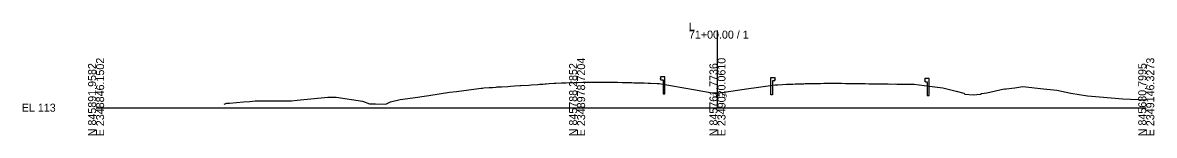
# Model space of a CAD drawing. Extents: x -26 to 2348767, y -10 to 845205.
# Drawn here: x 2164.2 to 2560.2, y 6490.3 to 6529.8 of the extents above; entities that cross this region are included whole.
import ezdxf

# ---------------------------------------------------------------- set-up
doc = ezdxf.new("R2010")
doc.units = 0
for name, color, linetype in [('Exist Cross Section Cell', 7, 'Continuous'), ('Exist XS Center Line Elevation Label', 7, 'Continuous'), ('Exist XS Ground Line', 7, 'Continuous'), ('Prop CMT Guardrail Graphics', 7, 'Continuous')]:
    doc.layers.add(name, color=color, linetype=linetype)

msp = doc.modelspace()

# ---------------------------------------------------------------- linework, layer by layer
at = {"layer": 'Exist Cross Section Cell'}
for p, q in [((2407.33, 6500), (2407.33, 6526.98)), ((2189.93, 6500), (2358.22, 6500)), ((2358.22, 6500), (2407.33, 6500)), ((2407.33, 6500), (2557.33, 6500))]:
    msp.add_line(p, q, dxfattribs=at)
at = {"layer": 'Exist XS Ground Line'}
msp.add_lwpolyline([(2234.77, 6501.29), (2235.73, 6501.56), (2236.65, 6501.57), (2241.48, 6502), (2243.77, 6502.17), (2245.57, 6502.35), (2257.71, 6502.45), (2258.27, 6502.45), (2260.25, 6502.63), (2270.96, 6503.63), (2273.95, 6503.67), (2283.09, 6502.28), (2285.56, 6501.35), (2287.68, 6501.32), (2291.32, 6501.26), (2292.94, 6502.03), (2296.35, 6502.84), (2300.77, 6503.43), (2306.35, 6504.25), (2313.6, 6505.39), (2316.07, 6505.7), (2324.68, 6506.87), (2325.16, 6506.88), (2325.59, 6506.91), (2327.44, 6507.05), (2328.6, 6507.12), (2329.89, 6507.24), (2330.3, 6507.26), (2331.73, 6507.33), (2333.98, 6507.47), (2334.92, 6507.53), (2336.31, 6507.61), (2338.19, 6507.73), (2338.56, 6507.75), (2341.27, 6507.93), (2342.13, 6508), (2344.44, 6508.17), (2345.2, 6508.23), (2346.18, 6508.29), (2347, 6508.35), (2347.44, 6508.38), (2348.45, 6508.45), (2350.21, 6508.53), (2350.81, 6508.57), (2352.75, 6508.68), (2353.3, 6508.71), (2354.3, 6508.74), (2357.18, 6508.81), (2358.41, 6508.84), (2360.21, 6508.89), (2363.2, 6508.96), (2365.26, 6508.99), (2366.17, 6508.99), (2366.71, 6508.99), (2367.67, 6508.97), (2369.11, 6508.95), (2370.33, 6508.93), (2372.29, 6508.9), (2373.98, 6508.86), (2375.06, 6508.84), (2376.17, 6508.82), (2377.4, 6508.79), (2378.04, 6508.76), (2379.41, 6508.73), (2381.26, 6508.68), (2381.63, 6508.67), (2383.04, 6508.62), (2383.94, 6508.6), (2386.2, 6508.49), (2386.93, 6508.43), (2398.92, 6506.39), (2406.76, 6505.02), (2407.33, 6505.1), (2416.65, 6506.47), (2427.45, 6508.04), (2428.08, 6508.02), (2428.39, 6508.05), (2430.07, 6508.14), (2431.43, 6508.2), (2432.48, 6508.24), (2433.71, 6508.28), (2434.46, 6508.31), (2437.48, 6508.41), (2438.01, 6508.43), (2440.39, 6508.47), (2441.8, 6508.5), (2442.75, 6508.51), (2443.37, 6508.52), (2444.55, 6508.53), (2446.39, 6508.54), (2449.46, 6508.54), (2449.82, 6508.53), (2450.7, 6508.53), (2452.12, 6508.52), (2453.48, 6508.51), (2455.65, 6508.49), (2457.18, 6508.46), (2458.22, 6508.44), (2459.03, 6508.43), (2460.25, 6508.41), (2461.21, 6508.39), (2461.52, 6508.38), (2461.82, 6508.37), (2464.12, 6508.35), (2464.85, 6508.34), (2466.23, 6508.33), (2467.09, 6508.31), (2467.79, 6508.29), (2469.62, 6508.3), (2470.04, 6508.29), (2471.02, 6508.28), (2473.05, 6508.26), (2474.09, 6508.24), (2475.51, 6508.19), (2476.18, 6508.19), (2479.63, 6507.78), (2486.2, 6506.93), (2490.81, 6505.82), (2493.5, 6505.04), (2493.86, 6504.75), (2496.76, 6504.48), (2499.37, 6504.77), (2499.7, 6504.91), (2501.57, 6505.24), (2507.66, 6506.65), (2507.98, 6506.47), (2508.34, 6506.63), (2511.4, 6506.9), (2514.16, 6507.41), (2521.4, 6506.64), (2526.04, 6506.11), (2531, 6505.13), (2536.76, 6504.11), (2540.94, 6503.75), (2549.11, 6503.15), (2557.33, 6502.8)], dxfattribs=at)
at = {"layer": 'Prop CMT Guardrail Graphics'}
for p, q in [((2387.6, 6510.86), (2387.33, 6510.57)), ((2387.33, 6510.57), (2387.6, 6510.28)), ((2387.6, 6510.28), (2387.33, 6509.99)), ((2387.33, 6509.99), (2387.6, 6509.7)), ((2388.94, 6510.86), (2387.6, 6510.86)), ((2387.6, 6509.7), (2388.27, 6509.7)), ((2388.27, 6509.7), (2388.27, 6504.86)), ((2388.94, 6504.86), (2388.94, 6510.86)), ((2425.94, 6504.55), (2425.94, 6510.55)), ((2425.94, 6510.55), (2427.27, 6510.55)), ((2427.27, 6509.39), (2426.6, 6509.39)), ((2426.6, 6509.39), (2426.6, 6504.55)), ((2427.27, 6510.55), (2427.54, 6510.26)), ((2427.54, 6510.26), (2427.27, 6509.97)), ((2427.27, 6509.97), (2427.54, 6509.68)), ((2427.54, 6509.68), (2427.27, 6509.39)), ((2480.07, 6510.26), (2479.8, 6509.97)), ((2479.8, 6509.97), (2480.07, 6509.68)), ((2480.07, 6509.68), (2479.8, 6509.39)), ((2479.8, 6509.39), (2480.07, 6509.09)), ((2481.41, 6510.26), (2480.07, 6510.26)), ((2481.41, 6504.26), (2481.41, 6510.26)), ((2480.07, 6509.09), (2480.74, 6509.09)), ((2480.74, 6509.09), (2480.74, 6504.26)), ((2388.27, 6504.86), (2388.94, 6504.86)), ((2426.6, 6504.55), (2425.94, 6504.55)), ((2480.74, 6504.26), (2481.41, 6504.26))]:
    msp.add_line(p, q, dxfattribs=at)

# ---------------------------------------------------------------- texts
at = {"layer": 'Exist Cross Section Cell'}
for s, p in [('L', (2397.33, 6526.98)), ('71+00.00 / 1', (2397.33, 6524.18)), ('EL 113', (2163.93, 6498.6))]:
    msp.add_text(s, height=2.8, dxfattribs=at).set_placement(p)
for s, p in [('E 2348846.1502', (2192.73, 6490)), ('E 2348978.7204', (2361.02, 6490)), ('E 2349020.0610', (2410.13, 6490)), ('E 2349146.3273', (2560.13, 6490)), ('N 845891.9582', (2189.93, 6490)), ('N 845788.2852', (2358.22, 6490)), ('N 845761.7736', (2407.33, 6490)), ('N 845680.7995', (2557.33, 6490))]:
    msp.add_text(s, height=2.8, rotation=90, dxfattribs=at).set_placement(p)
at = {"layer": 'Exist XS Center Line Elevation Label'}
msp.add_text('118.10', height=1.2, dxfattribs=at).set_placement((2405.52, 6503.5))

doc.saveas('drawing.dxf')
